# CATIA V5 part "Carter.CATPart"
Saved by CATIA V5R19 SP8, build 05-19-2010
Part number: Carter
Publications: "L", "dc", "e", "a", "r"
Bounding box of the stored display mesh (mm): x -90 to 50, y -250.167 to 250.167, z -173.301 to 260
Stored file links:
  C:\Users\ThinkMotion\Desktop\EU_thinkMotion\iao\IAO_MMS_Groupe3\evulliez\evulliez\evulliez\Mecanisme\Carter.CATPart
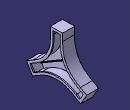
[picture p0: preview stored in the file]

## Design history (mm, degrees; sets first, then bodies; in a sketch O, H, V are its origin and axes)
Parameters
  L = 260 mm
  dc = 80 mm
  e = 10 mm
  a = 50 mm
  r = 10 mm
Body1 (main body)
  Point1: (0, 0, 0)
  Line1: type PtDir, RefPoint Point1, Direction (0, 0, 1), Start 0, End 250 {= L -e}
  Line2: type Angle, RefPoint Point1, Curve Line1, Support yz-plane, Start 0, End 250 {= L -e}, Angle 120
  Line3: type Angle, RefPoint Point1, Curve Line1, Support yz-plane, Start 0, End 250 {= L -e}, Angle -120
  Plane1: type Normal, Curve Line2, RefPoint vertex of Line2
  Plane2: type Normal, Curve Line3, RefPoint vertex of Line3
  Plane3: type Normal, Curve Line1, RefPoint vertex of Line1
  Line4: type PtDir, RefPoint Point1, Direction (1, 0, 0), Start -50, End 50 {= dc/2 +10mm}
  Sketch1 on yz-plane, origin (0, 0, 0), H (0, 1, 0), V (0, 0, 1)
    line L1 (196.5064, -159.641) -> (236.5064, -90.359)
    line L2 (-196.5064, -159.641) -> (-236.5064, -90.359)
    line L3 (40, 250) -> (-40, 250)
    reference intersected line E1 through (216.5064, -125) direction (0.5, 0.866) from Plane2
    reference intersected line E2 through (0, 250) direction (-1, 0) from Plane3
    reference intersected line E3 through (-216.5064, -125) direction (0.5, -0.866) from Plane1
    line L4 (40, 250) -> (40, 200)
    line L5 (-40, 250) -> (-40, 200)
    line L6 (236.5064, -90.359) -> (193.2051, -65.359)
    line L7 (196.5064, -159.641) -> (153.2051, -134.641)
    reference projected line E4 (0, 0) -> (182.7314, -105.5) from Line3
    reference projected line E5 (0, 0) -> (0, 211) from Line1
    line L8 (-196.5064, -159.641) -> (-153.2051, -134.641)
    line L9 (-236.5064, -90.359) -> (-193.2051, -65.359)
    reference projected line E6 (0, 0) -> (-182.7314, -105.5) from Line2
    connectcurve C1
    connectcurve C2
    connectcurve C3
    line L10 (200.1666, -173.3013) -> (250.1666, -86.6987)
    line L11 (250.1666, -86.6987) -> (198.2051, -56.6987)
    line L12 (200.1666, -173.3013) -> (148.2051, -143.3013)
    line L13 (-50, 260) -> (50, 260)
    line L14 (-50, 260) -> (-50, 200)
    line L15 (50, 260) -> (50, 200)
    line L16 (-250.1666, -86.6987) -> (-200.1666, -173.3013)
    point P21 (-250.1666, -86.6987)
    line L17 (-250.1666, -86.6987) -> (-198.2051, -56.6987)
    point P23 (-250.1666, -86.6987)
    line L18 (-200.1666, -173.3013) -> (-148.2051, -143.3013)
    connectcurve C4
    connectcurve C5
    connectcurve C6
    length L3 = 80 {= dc}
    length L1 = 80 {= dc}
    length L2 = 80 {= dc}
    distance E4 L6 = 40 {= dc /2}
    distance E5 L4 = 40 {= dc /2}
    distance E6 L9 = 40 {= dc /2}
    length L6 = 50 {= a}
    length L7 = 50 {= a}
    length L4 = 50 {= a}
    length L5 = 50 {= a}
    length L9 = 50 {= a}
    length L8 = 50 {= a}
    distance L6 L11 = 10 {= e}
    distance L10 L1 = 10 {= e}
    distance L12 L7 = 10 {= e}
    length L11 = 60 {= a +e}
    length L12 = 60 {= e +a}
    distance L3 L13 = 10 {= e}
    distance L4 L15 = 10 {= e}
    distance L5 L14 = 10 {= e}
    length L15 = 60 {= e +a}
    length L14 = 60 {= a +e}
    length L17 = 60 {= a +e}
    distance L2 L16 = 10 {= e}
    length L18 = 60 {= a +e}
    distance L17 L9 = 10 {= e}
    distance L8 L18 = 10 {= e}
    coincidence: E1 L1, L3 E2, E3 L2, P23 L16, P23 P21
    perpendicularity: L3 L4, L3 L5, L6 L1, L7 L1, L9 L2, L8 L2
    horizontal: L13 H
    vertical: L14 V, L15 V
  Pad1: profile Sketch1, direction (1, 0, 0), length 50 {= dc/2 +10mm}, mirrored extent
  Plane4: type OffsetPt, RefPlane yz-plane, RefPoint vertex of Line4
  Sketch2 on Plane4, origin (-50, 0, 0), H (0, 1, 0), V (0, 0, 1)
    line L1 (196.5064, -159.641) -> (236.5064, -90.359)
    line L2 (-196.5064, -159.641) -> (-236.5064, -90.359)
    line L3 (40, 250) -> (-40, 250)
    reference intersected line E1 through (216.5064, -125) direction (0.5, 0.866) from Plane2
    reference intersected line E2 through (0, 250) direction (-1, 0) from Plane3
    reference intersected line E3 through (-216.5064, -125) direction (0.5, -0.866) from Plane1
    line L4 (40, 250) -> (40, 200)
    line L5 (-40, 250) -> (-40, 200)
    line L6 (236.5064, -90.359) -> (193.2051, -65.359)
    line L7 (196.5064, -159.641) -> (153.2051, -134.641)
    reference projected line E4 (0, 0) -> (182.7314, -105.5) from Line3
    reference projected line E5 (0, 0) -> (0, 211) from Line1
    line L8 (-196.5064, -159.641) -> (-153.2051, -134.641)
    line L9 (-236.5064, -90.359) -> (-193.2051, -65.359)
    reference projected line E6 (0, 0) -> (-182.7314, -105.5) from Line2
    connectcurve C1
    connectcurve C2
    connectcurve C3
    point P13 (164.4301, -37.1987)
    length L3 = 80 {= dc}
    length L1 = 80 {= dc}
    length L2 = 80 {= dc}
    distance E4 L6 = 40 {= dc /2}
    distance E5 L4 = 40 {= dc /2}
    distance E6 L9 = 40 {= dc /2}
    length L6 = 50 {= a}
    length L7 = 50 {= a}
    length L4 = 50 {= a}
    length L5 = 50 {= a}
    length L9 = 50 {= a}
    length L8 = 50 {= a}
    coincidence: E1 L1, L3 E2, E3 L2
    perpendicularity: L3 L4, L3 L5, L6 L1, L7 L1, L9 L2, L8 L2
  Pad2: profile Sketch2, direction (1, 0, 0), length 10 {= e}
  Sketch3 on end face of Pad2, origin (-40, 0, 0), H (0, 1, 0), V (0, 0, 1)
    circle A1 centre (0, 0) radius 20
    radius A1 = 20 {= r +10mm}
  Pad3: profile Sketch3, direction (1, 0, 0), length 10 {= r}
  Line5: type PtDir, RefPoint vertex of Line4, Direction Plane4, Start 0, End 20 {= e +10mm}
  Sketch4 on end face of Pad2, origin (-40, 0, 0), H (0, 1, 0), V (0, 0, 1)
    line L1 (0, 10) -> (0, 250)
    point P1 (0, 10)
    point P2 (0, 250)
    reference projected point E1 (0, 250) from vertex of Line1
    reference projected line E2 (0, 0) -> (0, 235) from Line1
    line L2 (8.6603, -5) -> (216.5064, -125)
    point P3 (8.6603, -5)
    point P4 (216.5064, -125)
    line L3 (-8.6603, -5) -> (-216.5064, -125)
    point P5 (-8.6603, -5)
    point P6 (-216.5064, -125)
    reference projected point E3 (216.5064, -125) from vertex of Line3
    reference projected point E4 (0, 0) from Point1
    reference projected line E5 (0, 0) -> (203.516, -117.5) from Line3
    reference projected point E6 (0, 0) from Point1
    reference projected line E7 (0, 0) -> (-203.516, -117.5) from Line2
    reference projected point E8 (-216.5064, -125) from vertex of Line2
    distance H P1 = 10 {= r}
    distance P3 E4 = 10 {= r}
    distance E6 P5 = 10 {= r}
    coincidence: P2 E1, L1 E2, P4 E3, E5 L2, E7 L3, P6 E8
  Rib1: profile Sketch4, centre curve Line5, thin wall 5
  Sketch5 on face of Rib1, origin (-50, 0, 0), H (0, -1, 0), V (0, 0, 1)
    circle A1 centre (0, 0) radius 20
    point P1 (0, 0)
    reference projected point E1 (0, 0) from Point1
    radius A1 = 20 {= r +10mm}
    coincidence: E1 P1
  Pad4: profile Sketch5, direction (-1, 0, 0), length 40 {= 4*r}
  Sketch6 on end face of Pad4, origin (-90, 0, 0), H (0, 1, 0), V (0, 0, -1)
    point P1 (0, 0)
    reference projected point E1 (0, 0) from vertex of Line4
    coincidence: E1 P1
  Hole1: placed by Sketch6, at (-90, 0, 0) direction (1, 0, 0), diameter 20 {= 2*r}, through (limit type 3)
  Plane5: type Normal, Curve Line4, RefPoint vertex of Line4
  Sketch7 on Plane5, origin (50, 0, 0), H (0, 1, 0), V (0, 0, 1)
    line L1 (196.5064, -159.641) -> (236.5064, -90.359)
    line L2 (-196.5064, -159.641) -> (-236.5064, -90.359)
    line L3 (40, 250) -> (-40, 250)
    reference intersected line E1 through (216.5064, -125) direction (0.5, 0.866) from Plane2
    reference intersected line E2 through (0, 250) direction (-1, 0) from Plane3
    reference intersected line E3 through (-216.5064, -125) direction (0.5, -0.866) from Plane1
    line L4 (40, 250) -> (40, 200)
    line L5 (-40, 250) -> (-40, 200)
    line L6 (236.5064, -90.359) -> (193.2051, -65.359)
    line L7 (196.5064, -159.641) -> (153.2051, -134.641)
    reference projected line E4 (0, 0) -> (182.7314, -105.5) from Line3
    reference projected line E5 (0, 0) -> (0, 211) from Line1
    line L8 (-196.5064, -159.641) -> (-153.2051, -134.641)
    line L9 (-236.5064, -90.359) -> (-193.2051, -65.359)
    reference projected line E6 (0, 0) -> (-182.7314, -105.5) from Line2
    connectcurve C1
    connectcurve C2
    connectcurve C3
    line L10 (192.8461, -145.9808) -> (222.8461, -94.0192)
    line L11 (222.8461, -94.0192) -> (188.2051, -74.0192)
    line L12 (192.8461, -145.9808) -> (158.2051, -125.9808)
    line L13 (-30, 240) -> (30, 240)
    line L14 (-30, 240) -> (-30, 200)
    line L15 (30, 240) -> (30, 200)
    line L16 (-222.8461, -94.0192) -> (-192.8461, -145.9808)
    point P21 (-222.8461, -94.0192)
    line L17 (-222.8461, -94.0192) -> (-188.2051, -74.0192)
    point P23 (-222.8461, -94.0192)
    line L18 (-192.8461, -145.9808) -> (-158.2051, -125.9808)
    reference projected line E7 (0, 0) -> (203.516, -117.5) from Line3
    connectcurve C4
    connectcurve C5
    connectcurve C6
    length L3 = 80 {= dc}
    length L1 = 80 {= dc}
    length L2 = 80 {= dc}
    distance E4 L6 = 40 {= dc /2}
    distance E5 L4 = 40 {= dc /2}
    distance E6 L9 = 40 {= dc /2}
    length L6 = 50 {= a}
    length L7 = 50 {= a}
    length L4 = 50 {= a}
    length L5 = 50 {= a}
    length L9 = 50 {= a}
    length L8 = 50 {= a}
    length L11 = 40 {= a -e}
    length L12 = 40 {= a -e}
    distance L15 L4 = 10 {= e}
    distance L13 L3 = 10 {= e}
    distance L14 L5 = 10 {= e}
    length L15 = 40 {= a -e}
    length L14 = 40 {= a -e}
    length L17 = 40 {= a -e}
    distance L16 L2 = 10 {= e}
    length L18 = 40 {= a -e}
    distance L18 L8 = 10 {= e}
    distance L17 L9 = 10 {= e}
    distance L1 L10 = 10 {= e}
    distance L7 L12 = 10 {= e}
    distance L11 L6 = 10 {= e}
    coincidence: E1 L1, L3 E2, E3 L2, P23 L16, P23 P21
    perpendicularity: L3 L4, L3 L5, L6 L1, L7 L1, L9 L2, L8 L2
    horizontal: L13 H
    vertical: L14 V, L15 V
    parallelism: L12 E7
  Pad5: profile Sketch7, direction (-1, 0, 0), length 10 {= e}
